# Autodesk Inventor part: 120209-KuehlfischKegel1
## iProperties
Created: 2012-02
Part Number: 120209-KuehlfischKegel1
Document SubType Name: Modeling
Designer: mp
Density: 1 g/cm^3
Author: mp
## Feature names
1. Spiegeln2 [Mirror]
2. Rundung2 [Fillet]
3. Erhebung1
4. Rundung3 [Fillet]
5. Bohrung1 [Hole]
6. Spiegeln3 [Mirror]
7. Runde Anordnung1 [Circular Pattern]
